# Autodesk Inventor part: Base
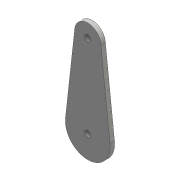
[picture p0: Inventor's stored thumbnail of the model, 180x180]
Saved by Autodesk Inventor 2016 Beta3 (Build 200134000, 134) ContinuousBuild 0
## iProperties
Created: 2016-03
Part Number: Base
Material: Generic
Document SubType Name: Modeling
Designer: Gaurav
Density: 1 g/cm^3
Appearance: Default
Author: Gaurav
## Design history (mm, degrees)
sketch "Sketch1"
  geometry: L1 (4.417, 15.746)-(7.453, -11.156); L2 (-4.417, 15.746)-(-7.453, -11.156); C1 r 1 at (0, 15.746); C2 r 1 at (0, -11.997); A1 r 4.417 centre (0, 15.746) between (4.417, 15.746) and (-4.417, 15.746); A2 r 7.5 centre (0, -11.997) between (-7.453, -11.156) and (7.453, -11.156); 1 further point
  constraints: 4 centre point, 4 end point, 4 point on circle, 2 coincident, 2 tangent
  dimensions: "d0" = 15 diameter of A2; "d1" = 2 diameter of C1; "d2" = 2 diameter of C2
extrude "Extrusion1" new body sketch "Sketch1" distance "d3" = 1.5; taper "d4" = 0 deg
body "Solid1"
